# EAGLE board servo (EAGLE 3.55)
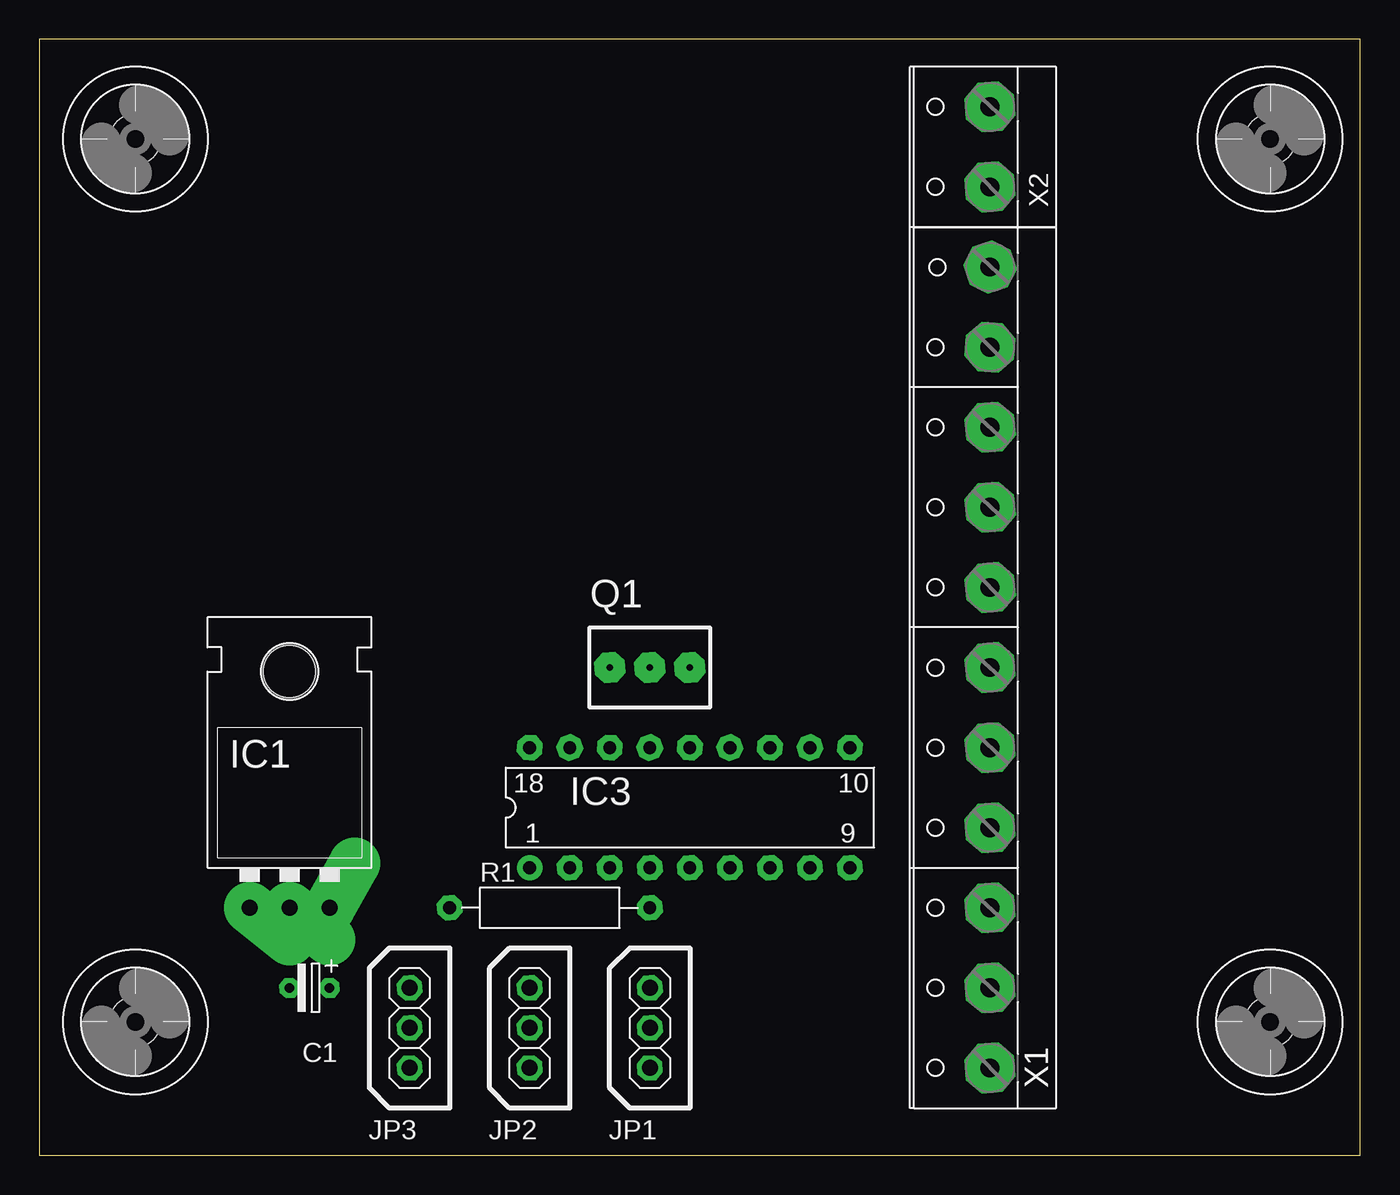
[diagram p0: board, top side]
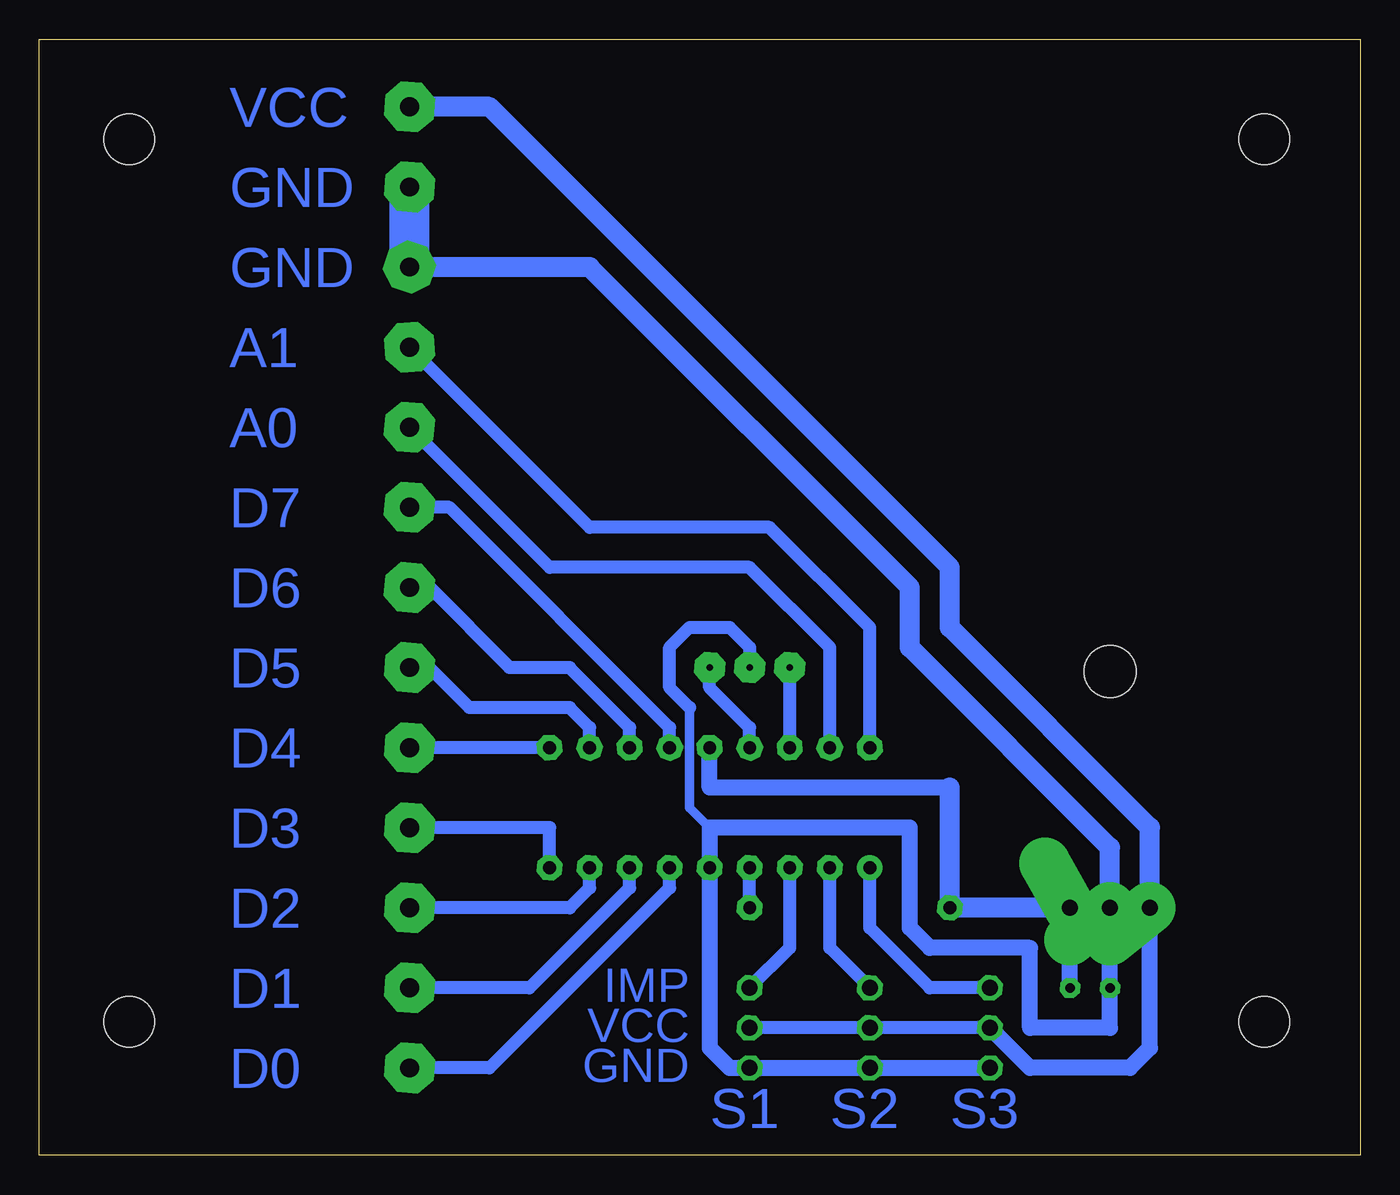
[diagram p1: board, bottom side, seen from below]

Size 83.8 x 70.79 mm. Coordinates in mm from the lower left corner, seen from the top.
Outline: 0,0 83.8,0 83.8,70.79 0,70.79 0,0
Copper layers used: Bottom

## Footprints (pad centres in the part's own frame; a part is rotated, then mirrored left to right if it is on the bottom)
-2,5 = drill 0.61 pad 1.27 octagon:  -1.27,0;  1.27,0
XXL = drill 1.016 pad 3.251 offset:  -2.54,-3.81;  0,-3.81;  2.54,-3.81 | hole 3.302: 0,11.176
L18 = drill 0.813 pad 1.6 round:  -10.16,-3.81 | drill 0.813 pad 1.6 octagon:  -7.62,-3.81;  -5.08,-3.81;  -2.54,-3.81;  0,-3.81;  2.54,-3.81;  5.08,-3.81;  7.62,-3.81;  10.16,-3.81;  10.16,3.81;  7.62,3.81;  5.08,3.81;  2.54,3.81;  0,3.81;  -2.54,3.81;  -5.08,3.81;  -7.62,3.81;  -10.16,3.81
03 = drill 1.016 pad 1.6 octagon:  -2.54,0;  0,0;  2.54,0
 = drill 0.406 pad 1.93 octagon:  0,0;  -2.54,0;  2.54,0
12,5 = drill 0.813 pad 1.6 octagon:  -6.35,0;  6.35,0
3,2S = hole 3.2: 0,0
37-11P = drill 1.194 pad 3.15 octagon:  -25.4,0;  -20.32,0;  -15.24,0;  -10.16,0;  -5.08,0;  0,0;  5.08,0;  10.16,0;  15.24,0;  20.32,0;  25.4,0
37-132 = drill 1.194 pad 3.15 octagon:  -2.54,0;  2.54,0

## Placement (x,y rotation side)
C1  10æ  [-2,5]  17.14,10.63 180 top
IC1  7805L  [XXL]  15.87,19.52 0 top
IC3  16F84P  [L18]  41.27,22.06 0 top
JP1  PINHD-1X3  [03]  38.73,8.09 90 top
JP2  PINHD-1X3  [03]  31.11,8.09 90 top
JP3  PINHD-1X3  [03]  23.49,8.09 90 top
Q1  4 MHz  []  38.73,30.95 0 top
R1  10k  [12,5]  32.38,15.71 0 top
U$2  [3,2S]  6.09,8.47 0 top
U$3  [3,2S]  78.09,8.47 0 top
U$4  [3,2S]  78.09,64.47 0 top
U$5  [3,2S]  6.09,64.47 0 top
X1  W237-11P  [37-11P]  60.32,30.95 90 top
X2  W237-02P  [37-132]  60.32,63.97 90 top

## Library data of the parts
C1 R1 = DISCRETE
IC1 = V-REG
IC3 = PIC
JP1-JP3 = PINHEAD
Q1 = Spezi
U$2-U$5 = HOLES
X1 X2 = WAGO508

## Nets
+5V: C1. IC1. IC3. R1.
A0: IC3. X1.
A1: IC3. X1.
D0: IC3. X1.
D1: IC3. X1.
D2: IC3. X1.
D3: IC3. X1.
D4: IC3. X1.
D5: IC3. X1.
D6: IC3. X1.
D7: IC3. X1.
GND: C1. IC1. IC3. JP1. JP2. JP3. Q1. X1. X2.
N$1: IC3. JP3.
N$2: IC3. Q1.
N$3: IC3. Q1.
N$4: IC3. JP2.
N$5: IC3. JP1.
N$6: IC3. R1.
VCC: IC1. JP1. JP2. JP3. X2.

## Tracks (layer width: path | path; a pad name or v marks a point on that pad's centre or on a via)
+5V
  Bottom 1.016: 18.41,10.63 IC1. | 41.27,25.87 41.27,23.33 26.03,23.33
  Bottom 1.27: IC1. 26.03,15.71 26.03,23.33
A0
  Bottom 0.813: 33.65,25.87 33.65,32.22 38.73,37.3 51.43,37.3 60.32,46.19
A1
  Bottom 0.813: IC3. 31.11,33.49 37.46,39.84 48.89,39.84 60.32,51.27
D0
  Bottom 0.813: 43.81,18.25 43.81,16.98 55.24,5.55 60.32,5.55
D1
  Bottom 0.813: 46.35,18.25 46.35,16.98 52.7,10.63 60.32,10.63
D2
  Bottom 0.813: 48.89,18.25 48.89,16.98 50.16,15.71 60.32,15.71
D3
  Bottom 0.813: 51.43,18.25 51.43,20.79 60.32,20.79
D4
  Bottom 0.813: 51.43,25.87 60.32,25.87
D5
  Bottom 0.813: 48.89,25.87 48.89,27.14 50.16,28.41 56.51,28.41 59.05,30.95 60.32,30.95
D6
  Bottom 0.813: 46.35,25.87 46.35,27.14 50.16,30.95 53.97,30.95 59.05,36.03 60.32,36.03
D7
  Bottom 0.813: 43.81,25.87 43.81,27.14 57.78,41.11 60.32,41.11
GND
  Bottom 0.61: 42.54,28.41 42.54,22.06 41.27,20.79
  Bottom 0.813: 42.54,28.41 43.81,29.68 43.81,32.22 42.54,33.49 40,33.49 38.73,32.22 38.73,30.95
  Bottom 1.016: 23.49,5.55 31.11,5.55 38.73,5.55 40,5.55 41.27,6.82 41.27,18.25 41.27,20.79 28.57,20.79 28.57,14.44 27.3,13.17 20.95,13.17 20.95,8.09 15.87,8.09 C1. 15.87,15.71
  Bottom 1.27: 15.87,14.44 15.87,15.71 15.87,19.52 28.57,32.22 28.57,36.03 48.89,56.35 X1.
  Bottom 2.54: X1. 60.32,61.43
N$1
  Bottom 0.813: JP3. 27.3,10.63 31.11,14.44 31.11,18.25
N$2
  Bottom 0.813: 36.19,25.87 36.19,30.95
N$3
  Bottom 0.813: 38.73,25.87 38.73,27.14 41.27,29.68 Q1.
N$4
  Bottom 0.813: 33.65,18.25 33.65,13.17 JP2.
N$5
  Bottom 0.813: 36.19,18.25 36.19,13.17 JP1.
N$6
  Bottom 0.813: R1. 38.73,18.25
VCC
  Bottom 0.813: 38.73,8.09 31.11,8.09 23.49,8.09
  Bottom 1.016: 23.49,8.09 20.95,5.55 14.6,5.55 13.33,6.82 13.33,15.71
  Bottom 1.27: 13.33,15.71 13.33,20.79 26.03,33.49 26.03,37.3 55.24,66.51 X2.

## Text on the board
Bottom: VCC | GND | GND | A1 | A0 | D7 | D6 | D5 | D4 | D3 | D2 | IMP | VCC | D1 | GND | D0 | S3 | S2 | S1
